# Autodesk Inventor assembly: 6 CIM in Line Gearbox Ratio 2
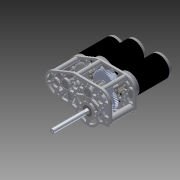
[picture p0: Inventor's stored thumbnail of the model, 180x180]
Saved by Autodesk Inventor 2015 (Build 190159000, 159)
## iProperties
Created: 2014-11
Part Number: 6 CIM in Line Gearbox Ratio 2
Document SubType Name: Assembly
Designer: Michael
Mass: 4438.01 g
Surface Area: 2514.13 cm^2
Volume: 1336.24 cm^3
Density: 3.32126 g/cm^3
Author: Michael
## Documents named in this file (30)
- C:\Users\User\Downloads\Pack ang Go 6 CIM 2 (2)\Pack ang Go 6 CIM 2\6 CIM in Line Gearbox Ratio 2.iam
- C:\Users\User\Downloads\Pack ang Go 6 CIM 2 (2)\Pack ang Go 6 CIM 2\Gearbox Plate Ratio 2.ipt
- C:\Users\User\Downloads\Pack ang Go 6 CIM 2 (2)\Pack ang Go 6 CIM 2\40T .5 inch.ipt
- C:\Users\User\Downloads\Pack ang Go 6 CIM 2 (2)\Pack ang Go 6 CIM 2\11t.ipt
- C:\Users\User\Downloads\Pack ang Go 6 CIM 2 (2)\Pack ang Go 6 CIM 2\50t.ipt
- C:\Users\User\Downloads\Pack ang Go 6 CIM 2 (2)\Pack ang Go 6 CIM 2\36t.ipt
- C:\Users\User\Downloads\Pack ang Go 6 CIM 2 (2)\Pack ang Go 6 CIM 2\217-2000 CIM motor.ipt
- C:\Users\User\Downloads\Pack ang Go 6 CIM 2 (2)\Pack ang Go 6 CIM 2\User Library-16T Gear AndyMark am-0747.ipt
- C:\Users\User\Downloads\Pack ang Go 6 CIM 2 (2)\Pack ang Go 6 CIM 2\40tDogGear.ipt
- C:\Users\User\Downloads\Pack ang Go 6 CIM 2 (2)\Pack ang Go 6 CIM 2\60tDogGear.ipt
- C:\Users\User\Downloads\Pack ang Go 6 CIM 2 (2)\Pack ang Go 6 CIM 2\Gearbox Plate Ratio 2 MIR.ipt
- C:\Users\User\Downloads\Pack ang Go 6 CIM 2 (2)\Pack ang Go 6 CIM 2\Standoff.ipt
- C:\Users\User\Downloads\Pack ang Go 6 CIM 2 (2)\Pack ang Go 6 CIM 2\Big Standoff.ipt
- C:\Users\User\Documents\Inventor\217-2428-027 Rev1_97414A630.ipt
- C:\Users\User\Documents\Inventor\217-3423-005 Rev1.ipt
- C:\Users\User\Documents\Inventor\217-3195-200 Rev1.iam
- C:\Users\User\Documents\Inventor\217-3489.ipt
- C:\Users\User\Documents\Inventor\217-3423-006 Rev1.ipt
- C:\Users\User\Documents\Inventor\217-3423-008 Rev1.ipt
- C:\Users\User\Documents\Inventor\217-2778-001 Rev2_NCQ8A075-050M.iam
- C:\Users\User\Documents\Inventor\217-3421-007 Rev1.ipt
- C:\Users\User\Documents\Inventor\217-3423-009 Rev1.ipt
- C:\Users\User\Documents\Inventor\217-3423-003 Rev1.ipt
- C:\Users\User\Documents\Inventor\217-2731.ipt
- C:\Users\User\Documents\Inventor\217-3423-004 Rev1.ipt
- C:\Users\User\Documents\Inventor\217-2743.ipt
- C:\Users\User\Documents\Inventor\217-2734.ipt
- C:\Users\User\Documents\Inventor\217-2733.ipt
- C:\Users\User\Downloads\217-2640-STEP-20140807\Imported Components\217-2640-STEP-20140807\217-2640-STEP-20140807.ipt
- C:\Users\User\Documents\6cim shaft.ipt
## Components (44 placed, 29 different names)
1. Gearbox Plate Ratio 2:1 — Mate:1, Mate:2, Mate:5, Mate:7, Mate:8, Mate:12, Mate:13, Mate:14, Mate:15, Mate:16, Mate:17, Mate:18, Mate:19, Mate:20, Mate:25, Mate:26, Angle:3, Mate:30, Mate:31, Mate:32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
2. 40T .5 inch:1 — Mate:2, Mate:10, Rotation:5, Rotation:6
3. 11t:1 — Mate:1, Mate:10, Flush:1, Rotation:5
4. 11t:2 — Mate:5, Flush:1, Flush:2, Rotation:6, Rotation:7, Flush:3
5. 50t:1 — Mate:7, Rotation:4, Mate:11, Angle:1, Mate:22, Rotation:7, Mate:24, Angle:2, Flush:3
6. 11t:3 — Mate:8, Rotation:4, Flush:2
7. 36t:1 — Mate:11, Angle:1, Mate:22, Rotation:8, Flush:4
8. 217-2000 CIM motor:1 — Mate:13, Mate:15, Mate:18
9. 217-2000 CIM motor:2 — Mate:14, Mate:16, Mate:19
10. 217-2000 CIM motor:3 — Mate:12, Mate:17, Mate:20
11. User Library-16T Gear AndyMark am-0747:1 — Mate:24, Angle:2, Rotation:9, Mate:81
12. 40tDogGear:1 — Mate:25, Rotation:8, Mate:71, Mate:72
13. 60tDogGear:1 — Mate:26, Angle:3, Rotation:9, Mate:76, Mate:77, Mate:81
14. Gearbox Plate Ratio 2 MIR:1 — Mate:30, Mate:31, Mate:32, Mate:36, Mate:37, Mate:38, Mate:66, Mate:79, Mate:80, Mate:82, Mate:83, Mate:87, Mate:88
15. Standoff:1 — Mate:35, Mate:36
16. Big Standoff:1 — Mate:33, Mate:34
17. Standoff:2 — Mate:41, Mate:42
18. Standoff:3 — Mate:39, Mate:40
19. Big Standoff:2 — Mate:37, Mate:38
20. 217-2428-027 Rev1_97414A630:1 — Mate:52, Mate:53
21. 217-3423-005 Rev1:1 — Mate:44, Mate:45, Mate:46, Mate:47, Mate:48, Mate:56, Mate:57, Mate:58
22. 217-3195-200 Rev1:1 [sub-assembly] — Mate:54, Mate:59, Mate:61
23. 217-3489:1 — Mate:50, Mate:51, Mate:54
24. 217-3423-006 Rev1:1 — Mate:55, Mate:58, Mate:63
25. 217-3423-006 Rev1:2 — Mate:43, Mate:46, Mate:60
26. 217-3423-008 Rev1:1 — Mate:49, Mate:50, Mate:51, Mate:52, Mate:53, Mate:59, Mate:64, Mate:65, Mate:68
27. 217-2778-001 Rev2_NCQ8A075-050M:1 [sub-assembly] — Mate:47, Mate:48, Mate:49, Mate:61
28. 217-3421-007 Rev1:1 — Mate:43, Mate:44, Mate:45
29. 217-3421-007 Rev1:2 — Mate:55, Mate:56, Mate:57, Mate:62
30. 217-3423-009 Rev1:1 — Mate:64, Mate:65
31. 217-3423-003 Rev1:1 — Mate:66, Mate:69, Mate:78
32. 217-2731:1 — Mate:67, Mate:68, Mate:70
33. 217-3423-004 Rev1:1 — Mate:69, Mate:70, Mate:75
34. 217-2743:1 — Mate:71, Mate:72, Mate:75, Flush:4
35. 217-2734:1 — Mate:76, Mate:77, Mate:78, Mate:92, Mate:93
36. 217-2734:2 — Mate:79, Mate:80
37. 217-2733:1 — Mate:82, Mate:87, Mate:95, Flush:6
38. 217-2733:2 — Mate:83, Mate:88, Mate:94, Flush:5
39. 217-2733:3 — Mate:85, Mate:86
40. 217-2733:4 — Mate:84, Mate:89
41. 217-2640-STEP-20140807:1 — Mate:90, Mate:91
42. 217-2640-STEP-20140807:2 — Mate:90, Mate:91, Mate:92, Mate:93
43. 6cim shaft:1 — Mate:94, Flush:5
44. 6cim shaft:3 — Mate:95, Flush:6
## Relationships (99: Mate 84, RelateRotation 6, Flush 6, Angle 3)
- Mate:1: Gearbox Plate Ratio 2:1 ↔ 11t:1
- Mate:2: Gearbox Plate Ratio 2:1 ↔ 40T .5 inch:1
- Mate:5: Gearbox Plate Ratio 2:1 ↔ 11t:2
- Mate:7: Gearbox Plate Ratio 2:1 ↔ 50t:1
- Mate:8: Gearbox Plate Ratio 2:1 ↔ 11t:3
- Mate:10: 40T .5 inch:1 ↔ 11t:1
- Rotation:4 [RelateRotation]: 50t:1 ↔ 11t:3
- Mate:11: 50t:1 ↔ 36t:1
- Angle:1: 50t:1 ↔ 36t:1
- Mate:12: Gearbox Plate Ratio 2:1 ↔ 217-2000 CIM motor:3
- Mate:13: Gearbox Plate Ratio 2:1 ↔ 217-2000 CIM motor:1
- Mate:14: Gearbox Plate Ratio 2:1 ↔ 217-2000 CIM motor:2
- Mate:15: Gearbox Plate Ratio 2:1 ↔ 217-2000 CIM motor:1
- Mate:16: Gearbox Plate Ratio 2:1 ↔ 217-2000 CIM motor:2
- Mate:17: Gearbox Plate Ratio 2:1 ↔ 217-2000 CIM motor:3
- Mate:18: Gearbox Plate Ratio 2:1 ↔ 217-2000 CIM motor:1
- Mate:19: Gearbox Plate Ratio 2:1 ↔ 217-2000 CIM motor:2
- Mate:20: Gearbox Plate Ratio 2:1 ↔ 217-2000 CIM motor:3
- Flush:1: 11t:1 ↔ 11t:2
- Flush:2: 11t:2 ↔ 11t:3
- Mate:22: 50t:1 ↔ 36t:1
- Rotation:5 [RelateRotation]: 40T .5 inch:1 ↔ 11t:1
- Rotation:6 [RelateRotation]: 40T .5 inch:1 ↔ 11t:2
- Rotation:7 [RelateRotation]: 11t:2 ↔ 50t:1
- Mate:24: 50t:1 ↔ User Library-16T Gear AndyMark am-0747:1
- Angle:2: 50t:1 ↔ User Library-16T Gear AndyMark am-0747:1
- Mate:25: Gearbox Plate Ratio 2:1 ↔ 40tDogGear:1
- Mate:26: Gearbox Plate Ratio 2:1 ↔ 60tDogGear:1
- Angle:3: Gearbox Plate Ratio 2:1 ↔ 60tDogGear:1
- Rotation:8 [RelateRotation]: 36t:1 ↔ 40tDogGear:1
- Rotation:9 [RelateRotation]: User Library-16T Gear AndyMark am-0747:1 ↔ 60tDogGear:1
- Mate:30: Gearbox Plate Ratio 2:1 ↔ Gearbox Plate Ratio 2 MIR:1
- Mate:31: Gearbox Plate Ratio 2:1 ↔ Gearbox Plate Ratio 2 MIR:1
- Mate:32: Gearbox Plate Ratio 2:1 ↔ Gearbox Plate Ratio 2 MIR:1
- Mate:33: Gearbox Plate Ratio 2:1 ↔ Big Standoff:1
- Mate:34: Gearbox Plate Ratio 2:1 ↔ Big Standoff:1
- Mate:35: Gearbox Plate Ratio 2:1 ↔ Standoff:1
- Mate:36: Gearbox Plate Ratio 2 MIR:1 ↔ Standoff:1
- Mate:37: Gearbox Plate Ratio 2 MIR:1 ↔ Big Standoff:2
- Mate:38: Gearbox Plate Ratio 2 MIR:1 ↔ Big Standoff:2
- Mate:39: Gearbox Plate Ratio 2:1 ↔ Standoff:3
- Mate:40: Gearbox Plate Ratio 2:1 ↔ Standoff:3
- Mate:41: Gearbox Plate Ratio 2:1 ↔ Standoff:2
- Mate:42: Gearbox Plate Ratio 2:1 ↔ Standoff:2
- Mate:43: 217-3423-006 Rev1:2 ↔ 217-3421-007 Rev1:1
- Mate:44: 217-3423-005 Rev1:1 ↔ 217-3421-007 Rev1:1
- Mate:45: 217-3423-005 Rev1:1 ↔ 217-3421-007 Rev1:1
- Mate:46: 217-3423-005 Rev1:1 ↔ 217-3423-006 Rev1:2
- Mate:47: 217-3423-005 Rev1:1 ↔ 217-2778-001 Rev2_NCQ8A075-050M:1
- Mate:48: 217-3423-005 Rev1:1 ↔ 217-2778-001 Rev2_NCQ8A075-050M:1
- Mate:49: 217-3423-008 Rev1:1 ↔ 217-2778-001 Rev2_NCQ8A075-050M:1
- Mate:50: 217-3489:1 ↔ 217-3423-008 Rev1:1
- Mate:51: 217-3489:1 ↔ 217-3423-008 Rev1:1
- Mate:52: 217-2428-027 Rev1_97414A630:1 ↔ 217-3423-008 Rev1:1
- Mate:53: 217-2428-027 Rev1_97414A630:1 ↔ 217-3423-008 Rev1:1
- Mate:54: 217-3195-200 Rev1:1 ↔ 217-3489:1
- Mate:55: 217-3423-006 Rev1:1 ↔ 217-3421-007 Rev1:2
- Mate:56: 217-3423-005 Rev1:1 ↔ 217-3421-007 Rev1:2
- Mate:57: 217-3423-005 Rev1:1 ↔ 217-3421-007 Rev1:2
- Mate:58: 217-3423-005 Rev1:1 ↔ 217-3423-006 Rev1:1
- Mate:59: 217-3195-200 Rev1:1 ↔ 217-3423-008 Rev1:1
- Mate:60: Gearbox Plate Ratio 2:1 ↔ 217-3423-006 Rev1:2
- Mate:61: 217-3195-200 Rev1:1 ↔ 217-2778-001 Rev2_NCQ8A075-050M:1
- Mate:62: Gearbox Plate Ratio 2:1 ↔ 217-3421-007 Rev1:2
- Mate:63: Gearbox Plate Ratio 2:1 ↔ 217-3423-006 Rev1:1
- Mate:64: 217-3423-008 Rev1:1 ↔ 217-3423-009 Rev1:1
- Mate:65: 217-3423-008 Rev1:1 ↔ 217-3423-009 Rev1:1
- Mate:66: Gearbox Plate Ratio 2 MIR:1 ↔ 217-3423-003 Rev1:1
- Mate:67: Gearbox Plate Ratio 2:1 ↔ 217-2731:1
- Mate:68: 217-3423-008 Rev1:1 ↔ 217-2731:1
- Mate:69: 217-3423-003 Rev1:1 ↔ 217-3423-004 Rev1:1
- Mate:70: 217-2731:1 ↔ 217-3423-004 Rev1:1
- Mate:71: 40tDogGear:1 ↔ 217-2743:1
- Mate:72: 40tDogGear:1 ↔ 217-2743:1
- Mate:75: 217-3423-004 Rev1:1 ↔ 217-2743:1
- Mate:76: 60tDogGear:1 ↔ 217-2734:1
- Mate:77: 60tDogGear:1 ↔ 217-2734:1
- Mate:78: 217-3423-003 Rev1:1 ↔ 217-2734:1
- Mate:79: Gearbox Plate Ratio 2 MIR:1 ↔ 217-2734:2
- Mate:80: Gearbox Plate Ratio 2 MIR:1 ↔ 217-2734:2
- Mate:81: User Library-16T Gear AndyMark am-0747:1 ↔ 60tDogGear:1
- Mate:82: Gearbox Plate Ratio 2 MIR:1 ↔ 217-2733:1
- Mate:83: Gearbox Plate Ratio 2 MIR:1 ↔ 217-2733:2
- Mate:84: Gearbox Plate Ratio 2:1 ↔ 217-2733:4
- Mate:85: Gearbox Plate Ratio 2:1 ↔ 217-2733:3
- Mate:86: Gearbox Plate Ratio 2:1 ↔ 217-2733:3
- Mate:87: Gearbox Plate Ratio 2 MIR:1 ↔ 217-2733:1
- Mate:88: Gearbox Plate Ratio 2 MIR:1 ↔ 217-2733:2
- Mate:89: Gearbox Plate Ratio 2:1 ↔ 217-2733:4
- Mate:90: 217-2640-STEP-20140807:1 ↔ 217-2640-STEP-20140807:2
- Mate:91: 217-2640-STEP-20140807:1 ↔ 217-2640-STEP-20140807:2
- Mate:92: 217-2734:1 ↔ 217-2640-STEP-20140807:2
- Mate:93: 217-2734:1 ↔ 217-2640-STEP-20140807:2
- Flush:3: 11t:2 ↔ 50t:1
- Flush:4: 36t:1 ↔ 217-2743:1
- Mate:94: 217-2733:2 ↔ 6cim shaft:1
- Flush:5: 217-2733:2 ↔ 6cim shaft:1
- Mate:95: 217-2733:1 ↔ 6cim shaft:3
- Flush:6: 217-2733:1 ↔ 6cim shaft:3
